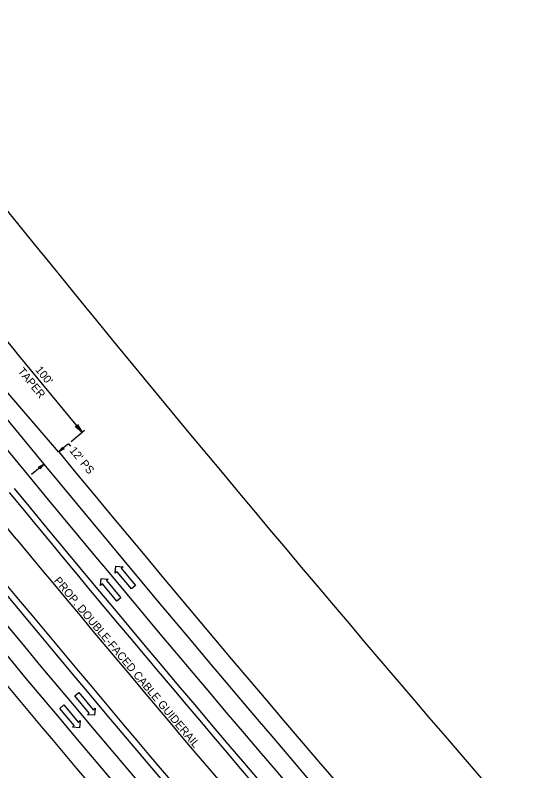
# Model space of a CAD drawing. Extents: x 1602193 to 1605074, y 908180 to 910630.
# Drawn here: x 1602582 to 1602900, y 909910.6 to 910382.6 of the extents above; entities that cross this region are included whole.
import ezdxf

# ---------------------------------------------------------------- set-up
doc = ezdxf.new("R2010")
doc.units = 0
for name, color, linetype in [('Prop Cable Guiderail Anchor Unit CELL', 7, 'Continuous'), ('Prop Cable Guiderail Double Face', 7, 'Continuous'), ('Prop Dimension', 7, 'Continuous'), ('Prop Dimension Text', 7, 'Continuous'), ('Prop DSN Text', 7, 'Continuous'), ('Prop EOT', 7, 'Continuous'), ('Prop Fence Woven Wire', 7, 'Continuous'), ('Prop Lane Arrow CELL', 7, 'Continuous'), ('Prop Lane Lines', 7, 'Continuous'), ('Prop Paved Shoulder', 7, 'Continuous')]:
    doc.layers.add(name, color=color, linetype=linetype)

msp = doc.modelspace()

# ---------------------------------------------------------------- linework, layer by layer
at = {"layer": 'Prop Cable Guiderail Anchor Unit CELL'}
msp.add_line((1602582.62, 910055.58), (1602572.43, 910067.91), dxfattribs=at)
at = {"layer": 'Prop Cable Guiderail Double Face'}
msp.add_arc((1613646.31, 919202), 14354.86, 219.580763, 222.768936, dxfattribs=at)
at = {"layer": 'Prop Dimension'}
for p, q in [((1602625.3, 910123.13), (1602616.88, 910116.19)), ((1602615.34, 910114.92), (1602609.16, 910109.83)), ((1602592.18, 910095.85), (1602599.9, 910102.2))]:
    msp.add_line(p, q, dxfattribs=at)
msp.add_arc((1613646.31, 919202), 14280.96, 219.081951, 219.480979, dxfattribs=at)
at = {"layer": 'Prop Dimension Text'}
msp.add_line((1602615.34, 910114.92), (1602616.61, 910113.38), dxfattribs=at)
at = {"layer": 'Prop DSN Text'}
for points in [[(1602620.9, 910126.89), (1602623.75, 910121.85), (1602619.36, 910125.62), (1602620.57, 910125.72)], [(1602612.52, 910111.74), (1602609.16, 910109.83), (1602611.67, 910112.77), (1602611.74, 910111.95)], [(1602596.54, 910100.3), (1602599.9, 910102.2), (1602597.39, 910099.27), (1602597.33, 910100.08)]]:
    msp.add_lwpolyline(points, close=True, dxfattribs=at)
at = {"layer": 'Prop EOT'}
msp.add_line((1602409.25, 910332.64), (1602599.88, 910102.22), dxfattribs=at)
for radius, start, end in [(14311.86, 219.480877, 227.661141), (14335.86, 219.480979, 227.66104), (14381.86, 219.480979, 227.66104), (14405.86, 219.479716, 227.662303)]:
    msp.add_arc((1613646.31, 919202), radius, start, end, dxfattribs=at)
at = {"layer": 'Prop Fence Woven Wire'}
for centre, radius, start, end in [((1613597.21, 919158.4), 14163.95, 218.093461, 222.076817), ((1613600.64, 919155.95), 14423.95, 219.415042, 223.36309)]:
    msp.add_arc(centre, radius, start, end, dxfattribs=at)
at = {"layer": 'Prop Lane Arrow CELL'}
for p, q in [((1602644.52, 910034.07), (1602644.9, 910038.47)), ((1602644.9, 910038.47), (1602649.37, 910038.09)), ((1602649.37, 910038.09), (1602648.22, 910037.13)), ((1602645.68, 910035.03), (1602644.52, 910034.07)), ((1602654.61, 910024.25), (1602645.68, 910035.03)), ((1602648.22, 910037.13), (1602657.15, 910026.35)), ((1602635.3, 910026.39), (1602635.68, 910030.79)), ((1602635.68, 910030.79), (1602640.15, 910030.41)), ((1602640.15, 910030.41), (1602639, 910029.45)), ((1602639, 910029.45), (1602647.93, 910018.67)), ((1602636.46, 910027.35), (1602635.3, 910026.39)), ((1602645.39, 910016.56), (1602636.46, 910027.35)), ((1602657.15, 910026.35), (1602654.61, 910024.25)), ((1602647.93, 910018.67), (1602645.39, 910016.56)), ((1602619.25, 909957.43), (1602621.79, 909959.54)), ((1602621.79, 909959.54), (1602630.75, 909948.79)), ((1602628.22, 909946.67), (1602619.25, 909957.43)), ((1602609.93, 909949.68), (1602612.47, 909951.79)), ((1602618.89, 909938.93), (1602609.93, 909949.68)), ((1602612.47, 909951.79), (1602621.43, 909941.04)), ((1602630.75, 909948.79), (1602631.9, 909949.75)), ((1602631.9, 909949.75), (1602631.54, 909945.34)), ((1602627.06, 909945.71), (1602628.22, 909946.67)), ((1602631.54, 909945.34), (1602627.06, 909945.71)), ((1602617.74, 909937.97), (1602618.89, 909938.93)), ((1602621.43, 909941.04), (1602622.58, 909942)), ((1602622.58, 909942), (1602622.22, 909937.59)), ((1602622.22, 909937.59), (1602617.74, 909937.97))]:
    msp.add_line(p, q, dxfattribs=at)
at = {"layer": 'Prop Lane Lines'}
msp.add_line((1602399.83, 910325.2), (1602590.64, 910094.57), dxfattribs=at)
for radius in [14323.86, 14393.86]:
    msp.add_arc((1613646.31, 919202), radius, 219.480979, 227.66104, dxfattribs=at)
at = {"layer": 'Prop Paved Shoulder'}
msp.add_line((1602609.16, 910109.83), (1602544.12, 910185.31), dxfattribs=at)
for radius, start, end in [(14299.86, 219.480979, 223.794464), (14339.86, 219.480979, 222.863015), (14377.86, 219.48119, 222.373049), (14417.86, 219.480979, 222.382421)]:
    msp.add_arc((1613646.31, 919202), radius, start, end, dxfattribs=at)

# ---------------------------------------------------------------- texts
at = {"layer": 'Prop Cable Guiderail Double Face'}
msp.add_text('PROP. DOUBLE-FACED CABLE GUIDERAIL', height=5, rotation=310.0391, dxfattribs=at).set_placement((1602605.89, 910029.25))
at = {"layer": 'Prop Dimension'}
for s, rotation, p in [('TAPER', 309.285, (1602583.34, 910160.07)), ("100'", 309.288, (1602594.29, 910160.9))]:
    msp.add_text(s, height=5, rotation=rotation, dxfattribs=at).set_placement(p)
at = {"layer": 'Prop Dimension Text'}
msp.add_text("12' PS", height=5, rotation=309.481, dxfattribs=at).set_placement((1602615.58, 910110.54))

doc.saveas('drawing.dxf')
